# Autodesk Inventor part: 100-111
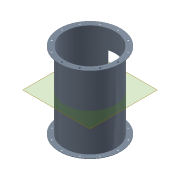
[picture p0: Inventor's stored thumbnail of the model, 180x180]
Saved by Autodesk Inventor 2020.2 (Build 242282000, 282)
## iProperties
Created: 2011-01
Part Number: 100-111
Document SubType Name: Modeling
Designer: F.Stasiak
Density: 1 g/cm^3
Material: Ogólny
Appearance: Stalowoniebieska
Company: Fabian Stasiak CAD Consulting
Manager: www.cadconsulting.pl
Author: F.Stasiak
Subject: Zbiór ćwiczeń. Autodesk Inventor 2020. Kurs podstawowy
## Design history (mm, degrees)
sketch "Szkic1"
  geometry: C1 r 200 at (0, 0); C2 r 197 at (0, 0); 1 further point
  constraints: 2 centre point, 2 coincident
  dimensions: "d0" = 400 diameter of C1; "d1" = 3 radial gap between concentric circles of C1 C2
extrude "Wyciągnięcie proste1" new body sketch "Szkic1" distance "d2" = 600; taper "d3" = 0 deg
sketch "Szkic2"
  geometry: C1 r 200 at (0, 0) reference; C2 r 240 at (0, 0); 1 further point
  constraints: 1 centre point
  dimensions: "d4" = 40 radial gap between concentric circles of C2 C1
extrude "Wyciągnięcie proste2" join sketch "Szkic2" distance "d5" = 3; taper "d6" = 0 deg
sketch "Szkic3"
  geometry: C1 r 200 at (0, 0) reference; C2 r 240 at (0, 0); 1 further point
  constraints: 1 centre point
  dimensions: "d7" = 40 radial gap between concentric circles of C2 C1
extrude "Wyciągnięcie proste3" join sketch "Szkic3" distance "d8" = 3; taper "d9" = 0 deg
sketch "Szkic4"
  geometry: 2 further points
  dimensions: "d10" = 220 distance of point (0, 220) point (0, 0)
hole "Hole1" sketch "Szkic4" at (0, 220) diameter "d11" = 13; stored, may be unused: countersink angle "d15" = 90 deg, drill point angle "d17" = 118 deg; dims "d12" = 6, "d13" = 4, "d14" = 2, "d16" = 8
pattern_circular "Szyk kołowy1" dims angle "d19" = 360 deg
sketch "Szkic5"
  geometry: L1 (-50, 450)-(50, 450); L2 (50, 450)-(50, 150); L3 (50, 150)-(-50, 150); L4 (-50, 150)-(-50, 450); L5 (0, -70)-(0, 420) reference; L6 (197, 0)-(-197, 0) reference; 2 further points
  constraints: 8 end point, 2 parallel, 1 horizontal, 1 midpoint, 1 perpendicular, 1 point on line
  dimensions: "d21" = 100 distance of L2.end L3.end; "d22" = 300 distance of L1.end L2.end; "d23" = 150 distance between parallel lines of L6 L3 (computed from d2)
extrude "Wyciągnięcie proste4" cut sketch "Szkic5" extent not by distance; stored distance "d24" = 3; taper "d25" = 0 deg
node "Płaszczyzna konstrukcyjna1"
node "Bryła1"
